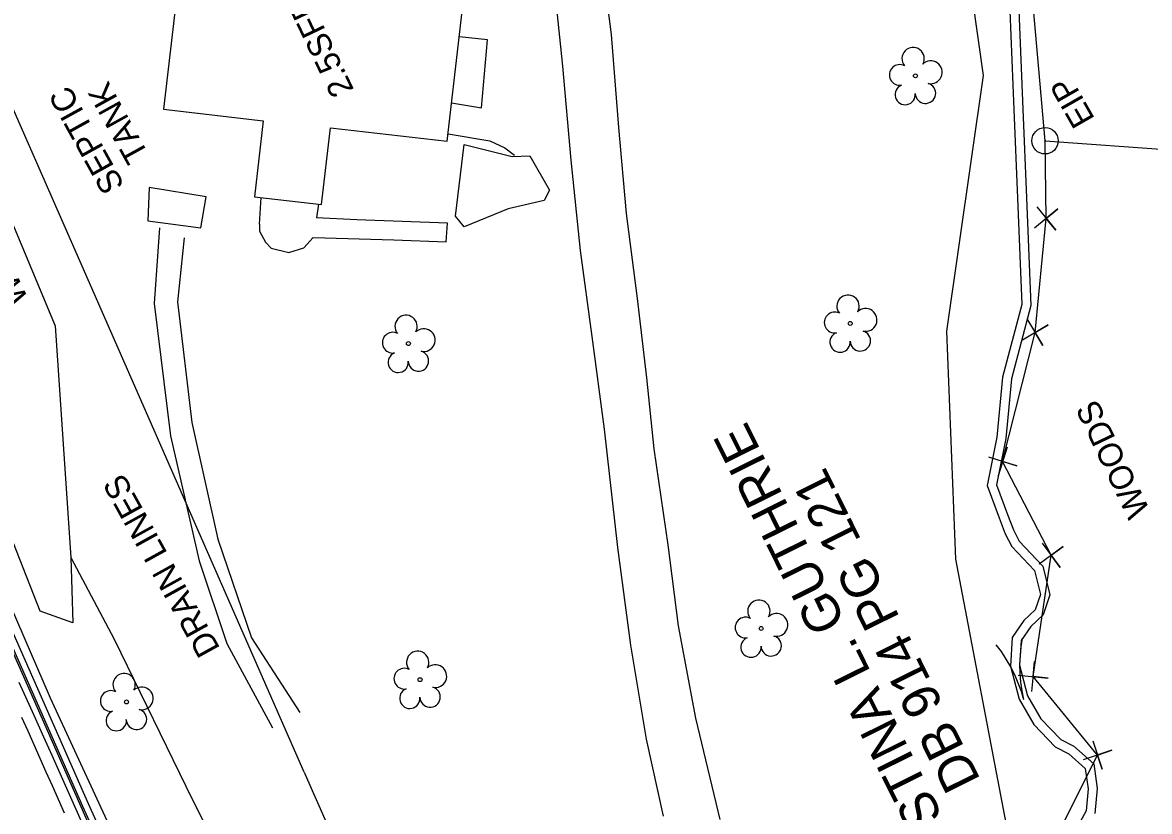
# Model space of a CAD drawing. Extents: x 472260 to 482161, y 489063 to 507124.
# Drawn here: x 475985.5 to 476173.2, y 501685.2 to 501816.7 of the extents above; entities that cross this region are included whole.
import ezdxf

# ---------------------------------------------------------------- set-up
doc = ezdxf.new("R2010")
doc.units = 0
for name, color, linetype in [('Exist Plan Preparation Watershed Blue', 7, 'Continuous'), ('Exist Roads EOP Other Cogo Number', 7, 'Continuous'), ('Exist Roads EOP Other Cogo Point CELL', 7, 'Continuous'), ('Exist Structure Minor Drop Inlet Cogo Comment', 7, 'Continuous'), ('Exist Structure Minor Drop Inlet Cogo Elevation', 7, 'Continuous'), ('Exist Structure Minor Drop Inlet Cogo Number', 7, 'Continuous'), ('Exist Structure Minor Pipes CMP 30 Inch Invert', 7, 'Continuous'), ('Exist Utilities Water Meter CELL', 7, 'Continuous'), ('Old_Level_51', 7, 'Continuous'), ('Prop Drainage Structure Catch Basin Convert From Junction Box Label', 7, 'Continuous'), ('Prop Drainage Structure Drop Inlet Grate 2 Narrow Slots and Sag Grates 840 24 CELL', 7, 'Continuous'), ('Prop Drainage Structure Drop Inlet Grate 2 Wide Slots and Flat Grates 840 20 Label', 7, 'Continuous'), ('Prop Drainage Structure Outlet Berm Ditch 850 10 CELL', 7, 'Continuous'), ('Prop Drainage Structure Pipe RCP 18in Class III', 7, 'Continuous'), ('Prop Drainage Structure Pipe RCP 24in Class III', 7, 'Continuous'), ('Prop Drainage Structure Pipe RCP 66in Class III', 7, 'Continuous'), ('Prop Drainage Structure Pipe Stub Out CELL', 7, 'Continuous'), ('Prop Drainage Structure Pipe Welded Steel 66in Label', 7, 'Continuous'), ('Prop Drainage Structure Plot Symbol 50 Scale CELL', 7, 'Continuous'), ('Prop Drainage Structure Tops and Inverts LABEL', 7, 'Continuous'), ('Prop Erosion Rip Rap Pad at Outlet Label', 7, 'Continuous'), ('Prop SS Cut Line', 7, 'Continuous'), ('Prop SS Fill Line', 7, 'Continuous'), ('Scratch_Level_7', 7, 'Continuous'), ('Scratch_Level_8', 7, 'Continuous')]:
    doc.layers.add(name, color=color, linetype=linetype)

msp = doc.modelspace()

# ---------------------------------------------------------------- linework, layer by layer
at = {"layer": 'Exist Plan Preparation Watershed Blue'}
for points in [[(476056.96, 501803.31), (476061.98, 501802.5), (476062.99, 501813.81), (476058.33, 501814.34)], [(476024.97, 501783.09), (476025.26, 501787.56)], [(476034.81, 501786.45), (476034.48, 501784.15)], [(476024.97, 501783.09), (476025.02, 501781.96), (476025.98, 501780.1), (476026.94, 501779.08), (476029.86, 501778.38), (476032.37, 501779.17), (476033.93, 501780.86), (476047.4, 501780.52), (476056.07, 501780.18), (476056.33, 501783.25), (476041.19, 501783.85), (476034.48, 501784.15)]]:
    msp.add_lwpolyline(points, dxfattribs=at)
at = {"layer": 'Exist Roads EOP Other Cogo Point CELL'}
for p, q in [((476156.05, 501784.05), (476156.05, 501784.05)), ((476154.22, 501765.03), (476154.22, 501765.03)), ((476148.79, 501743.56), (476148.79, 501743.56)), ((476156.88, 501727.91), (476156.88, 501727.91)), ((476153.87, 501707.7), (476153.87, 501707.7)), ((476164.59, 501694.62), (476164.59, 501694.62))]:
    msp.add_line(p, q, dxfattribs=at)
for points in [[(476154.46, 501785.98), (476157.64, 501782.12), (476156.05, 501784.05), (476157.98, 501785.64), (476154.12, 501782.46)], [(476152.94, 501767.18), (476155.5, 501762.88), (476154.22, 501765.03), (476156.37, 501766.31), (476152.08, 501763.75)], [(476146.41, 501744.32), (476151.18, 501742.8), (476148.79, 501743.56), (476149.55, 501745.95), (476148.04, 501741.18)], [(476155.4, 501729.92), (476158.37, 501725.9), (476156.88, 501727.91), (476158.89, 501729.4), (476154.87, 501726.42)], [(476151.38, 501707.95), (476156.35, 501707.46), (476153.87, 501707.7), (476154.11, 501710.19), (476153.62, 501705.22)], [(476163.81, 501696.99), (476165.38, 501692.25), (476164.59, 501694.62), (476166.97, 501695.41), (476162.22, 501693.83)]]:
    msp.add_lwpolyline(points, dxfattribs=at)
at = {"layer": 'Exist Structure Minor Drop Inlet Cogo Comment'}
for radius in [2.2, 0.0707]:
    msp.add_circle((476155.85, 501797.01), radius, dxfattribs=at)
at = {"layer": 'Exist Structure Minor Drop Inlet Cogo Elevation'}
msp.add_line((476032.41, 501691.77), (475818.42, 502179.8), dxfattribs=at)
msp.add_arc((478949.91, 502971.03), 3185.64, 203.67637, 207.50231, dxfattribs=at)
at = {"layer": 'Exist Structure Minor Drop Inlet Cogo Number'}
for p, q in [((476155.85, 501797.01), (476153.13, 501828.08)), ((476156.05, 501784.05), (476155.85, 501797.01)), ((476155.85, 501797.01), (476363.44, 501781.82)), ((476154.22, 501765.03), (476156.05, 501784.05)), ((476148.79, 501743.56), (476154.22, 501765.03)), ((476156.88, 501727.91), (476148.79, 501743.56)), ((476153.87, 501707.7), (476156.88, 501727.91)), ((476164.59, 501694.62), (476153.87, 501707.7)), ((476147.61, 501660.82), (476164.59, 501694.62))]:
    msp.add_line(p, q, dxfattribs=at)
at = {"layer": 'Exist Utilities Water Meter CELL'}
for points in [[(476008.34, 501782.5), (476007.43, 501769.91), (476010.17, 501747.81), (476014.97, 501727), (476019.54, 501713.2), (476027.14, 501699.18)], [(476012.47, 501780.85), (476011.36, 501770.18), (476013.73, 501750.07), (476018.08, 501730.61), (476023.67, 501714.17), (476031.72, 501701.71)]]:
    msp.add_lwpolyline(points, dxfattribs=at)
at = {"layer": 'Old_Level_51'}
msp.add_lwpolyline([(476016.1, 501787.65), (476006.64, 501789.24), (476006.38, 501783.69), (476015.2, 501782.49), (476016.1, 501787.65)], dxfattribs=at)
at = {"layer": 'Prop Drainage Structure Catch Basin Convert From Junction Box Label'}
for points in [[(476023.09, 501628.04), (476010.56, 501655.36), (475996.5, 501686.48), (475969.69, 501747.26), (475956.67, 501777.09), (475945.34, 501802.97), (475931.42, 501835.01), (475919.05, 501863.11), (475906.12, 501892.94), (475902.03, 501902.25)], [(476022.19, 501627.62), (476009.65, 501654.95), (475995.58, 501686.07), (475968.77, 501746.86), (475955.75, 501776.69), (475944.43, 501802.57), (475930.5, 501834.61), (475918.13, 501862.71), (475906.55, 501889.43)]]:
    msp.add_lwpolyline(points, dxfattribs=at)
at = {"layer": 'Prop Drainage Structure Drop Inlet Grate 2 Narrow Slots and Sag Grates 840 24 CELL'}
msp.add_lwpolyline([(475992.51, 501684.91), (475991.5, 501687.19), (475990.49, 501689.47), (475989.47, 501691.75), (475988.46, 501694.03), (475987.45, 501696.32), (475986.44, 501698.6), (475985.43, 501700.88)], dxfattribs=at)
at = {"layer": 'Prop Drainage Structure Drop Inlet Grate 2 Wide Slots and Flat Grates 840 20 Label'}
for p, q in [((476134.26, 501807.83), (476134.26, 501807.83)), ((476123.41, 501766.56), (476123.41, 501766.56)), ((476049.8, 501763.2), (476049.8, 501763.2)), ((476108.57, 501715.72), (476108.57, 501715.72)), ((476051.74, 501707.19), (476051.74, 501707.19)), ((476002.84, 501703.47), (476002.84, 501703.47))]:
    msp.add_line(p, q, dxfattribs=at)
for centre in [(476134.26, 501807.83), (476123.41, 501766.56), (476049.8, 501763.2), (476108.57, 501715.72), (476051.74, 501707.19), (476002.84, 501703.47)]:
    msp.add_circle(centre, 0.326, dxfattribs=at)
for centre, radius, start, end in [((476133.88, 501810.7), 1.86, 330.1651, 219.7134), ((476136.81, 501808.42), 1.9, 257.1011, 134.1999), ((476131.66, 501807.98), 1.73, 62.6636, 279.3457), ((476135.94, 501804.93), 1.7, 181.2822, 74.56), ((476132.56, 501804.71), 1.69, 111.5671, 6.231), ((476123.03, 501769.44), 1.86, 330.1651, 219.7134), ((476125.96, 501767.15), 1.9, 257.1011, 134.1999), ((476049.41, 501766.07), 1.86, 330.1651, 219.7134), ((476120.81, 501766.72), 1.73, 62.6636, 279.3457), ((476047.19, 501763.35), 1.73, 62.6636, 279.3457), ((476052.35, 501763.78), 1.9, 257.1011, 134.1999), ((476125.09, 501763.66), 1.7, 181.2822, 74.56), ((476121.71, 501763.44), 1.69, 111.5671, 6.231), ((476048.1, 501760.07), 1.69, 111.5671, 6.231), ((476051.47, 501760.3), 1.7, 181.2822, 74.56), ((476108.19, 501718.59), 1.86, 330.1651, 219.7134), ((476111.12, 501716.31), 1.9, 257.1011, 134.1999), ((476105.97, 501715.87), 1.73, 62.6636, 279.3457), ((476110.24, 501712.82), 1.7, 181.2822, 74.56), ((476106.87, 501712.6), 1.69, 111.5671, 6.231), ((476051.35, 501710.07), 1.86, 330.1651, 219.7134), ((476049.13, 501707.35), 1.73, 62.6636, 279.3457), ((476054.28, 501707.78), 1.9, 257.1011, 134.1999), ((476002.45, 501706.35), 1.86, 330.1651, 219.7134), ((476000.23, 501703.63), 1.73, 62.6636, 279.3457), ((476005.39, 501704.06), 1.9, 257.1011, 134.1999), ((476050.03, 501704.07), 1.69, 111.5671, 6.231), ((476053.41, 501704.29), 1.7, 181.2822, 74.56), ((476001.13, 501700.35), 1.69, 111.5671, 6.231), ((476004.51, 501700.57), 1.7, 181.2822, 74.56)]:
    msp.add_arc(centre, radius, start, end, dxfattribs=at)
at = {"layer": 'Prop Drainage Structure Pipe RCP 18in Class III'}
for points in [[(476081.6, 501830.22), (476083.56, 501814.7), (476084.8, 501799.24), (476086.08, 501784.87), (476087.92, 501770.74), (476089.49, 501757.5), (476090.7, 501745.66), (476093, 501729.64), (476094.73, 501716.14), (476097.61, 501700.79), (476101.69, 501683.88)], [(476092.31, 501684.44), (476089.46, 501697.28), (476086.83, 501712.92), (476084.68, 501729.2), (476082.47, 501748.93), (476080.42, 501764.36), (476078.47, 501778.7), (476076.9, 501793.78), (476075.53, 501809.47), (476074.4, 501820.17)]]:
    msp.add_lwpolyline(points, dxfattribs=at)
at = {"layer": 'Prop Drainage Structure Pipe RCP 24in Class III'}
for points in [[(476149.82, 501822.82), (476150.66, 501802.24), (476151.24, 501787.46), (476151.99, 501769.69), (476148.76, 501757.6), (476147.82, 501747.59), (476146.22, 501739.55), (476148.21, 501734.17), (476149.22, 501731.52), (476150.34, 501729.38), (476154.1, 501725.37)], [(476151.32, 501822.93), (476152.16, 501802.3), (476152.74, 501787.52), (476153.5, 501769.53), (476150.24, 501757.33), (476149.31, 501747.37), (476147.78, 501739.67), (476149.61, 501734.7), (476150.59, 501732.14), (476151.57, 501730.26), (476155.46, 501726.12)], [(476155.46, 501726.12), (476156.66, 501721.33), (476155.53, 501717.98), (476153.47, 501716.05), (476151.86, 501713.71), (476151.6, 501709.61), (476152.93, 501704.48), (476155.18, 501700.64), (476158.46, 501697.21), (476160.64, 501696.08), (476163.96, 501693.14), (476164.53, 501689.03), (476164.14, 501684.88)], [(476154.1, 501725.37), (476155.1, 501721.39), (476154.23, 501718.82), (476152.33, 501717.03), (476150.39, 501714.21), (476150.09, 501709.46), (476151.53, 501703.91), (476153.97, 501699.73), (476157.55, 501696), (476159.79, 501694.83), (476162.55, 501692.38), (476163.02, 501688.99), (476162.68, 501685.32), (476161.1, 501682.36)]]:
    msp.add_lwpolyline(points, dxfattribs=at)
at = {"layer": 'Prop Drainage Structure Pipe Stub Out CELL'}
msp.add_lwpolyline([(475984.92, 501706.77), (475986.31, 501703.71), (475987.68, 501700.66), (475989.04, 501697.63), (475990.38, 501694.62), (475991.71, 501691.61), (475993.05, 501688.61), (475994.38, 501685.61), (475995.71, 501682.61)], dxfattribs=at)
at = {"layer": 'Prop Drainage Structure Plot Symbol 50 Scale CELL'}
msp.add_lwpolyline([(475858.22, 502003.88), (475873.57, 501964.57), (475891.99, 501921.71), (475909.74, 501881.21), (475923.46, 501849.74), (475940.91, 501809.98), (475962.4, 501760.56), (475980.02, 501720.44), (476000.62, 501673.83), (476022.76, 501626.04)], dxfattribs=at)
at = {"layer": 'Prop Drainage Structure Tops and Inverts LABEL'}
for points in [[(476022.28, 501634.99), (476006.38, 501668.99), (475990.19, 501704.12), (475956.28, 501782.58), (475939.62, 501821.15), (475932.88, 501836.43), (475938.29, 501838.59)], [(476057.63, 501784.45), (476059.07, 501796.41), (476067.09, 501794.36), (476070.05, 501794.52), (476073.33, 501788.76), (476072.41, 501787.04), (476066.4, 501785.69), (476059.1, 501782.68), (476057.63, 501784.45)], [(475993.54, 501727.54), (476000.81, 501713.95), (476013.85, 501687.14), (476026.43, 501662.24), (476033.03, 501643.73)]]:
    msp.add_lwpolyline(points, dxfattribs=at)
at = {"layer": 'Prop Erosion Rip Rap Pad at Outlet Label'}
for points in [[(476140.99, 501727.29), (476139.47, 501765.27), (476145.59, 501807.86), (476138.11, 501860.9), (476086.9, 501921.65), (476072.81, 501972.58), (476078.45, 501996.77), (476071.32, 502007.46), (476040.62, 501992.73), (475998.06, 501960.08), (475920.84, 501910.21)], [(475977.25, 501798.93), (475990.98, 501766.15), (475993.54, 501727.54), (475993.91, 501716.65), (475988.46, 501718.62), (475952.41, 501810.41)], [(476187.79, 501751.97), (476187.19, 501730.04), (476202.62, 501717.27), (476190.92, 501678.08), (476166.08, 501679.55), (476149.37, 501683.26), (476140.99, 501727.29)]]:
    msp.add_lwpolyline(points, dxfattribs=at)
at = {"layer": 'Prop SS Fill Line'}
msp.add_lwpolyline([(476056.26, 501796.92), (476060.39, 501832.55), (476013.18, 501838.03), (476009.03, 501802.25), (476025.63, 501800.33), (476024.17, 501787.69), (476035.35, 501786.39), (476036.83, 501799.17)], close=True, dxfattribs=at)
msp.add_lwpolyline([(476056.4, 501798.15), (476063.38, 501796.99), (476065.84, 501795.82), (476067.45, 501794.63)], dxfattribs=at)
at = {"layer": 'Scratch_Level_8'}
msp.add_line((476151.06, 501708.72), (476151.06, 501708.72), dxfattribs=at)
for points in [[(476147.63, 501713.01), (476148.53, 501711.86), (476149.33, 501710.59), (476150.1, 501709.33), (476150.74, 501708.03), (476151.33, 501706.67), (476151.85, 501705.27), (476152.28, 501703.87)], [(476152.06, 501714.12), (476151.81, 501712.68), (476151.7, 501711.18), (476151.62, 501709.71), (476151.66, 501708.26), (476151.79, 501706.79), (476151.99, 501705.3), (476152.28, 501703.87)]]:
    msp.add_lwpolyline(points, dxfattribs=at)

# ---------------------------------------------------------------- texts
at = {"layer": 'Exist Roads EOP Other Cogo Number'}
msp.add_text('EIP', height=4, rotation=119.7387, dxfattribs=at).set_placement((476164.23, 501800.65))
at = {"layer": 'Exist Structure Minor Pipes CMP 30 Inch Invert'}
for s, p in [('TANK', (476006.64, 501794.65)), ('SEPTIC', (476002.59, 501789.57))]:
    msp.add_text(s, height=4, rotation=118.9347, dxfattribs=at).set_placement(p)
at = {"layer": 'Prop Drainage Structure Outlet Berm Ditch 850 10 CELL'}
msp.add_text('2.5SFBKD', height=4, rotation=115.5025, dxfattribs=at).set_placement((476040.79, 501805.49))
at = {"layer": 'Prop Drainage Structure Pipe RCP 66in Class III'}
for p in [(475986.6, 501770.52), (476173.42, 501735.32)]:
    msp.add_text('WOODS', height=4, rotation=115.5025, dxfattribs=at).set_placement(p)
at = {"layer": 'Prop Drainage Structure Pipe Welded Steel 66in Label'}
msp.add_text('DB 914 PG 121', height=6.25, rotation=116.4407, dxfattribs=at).set_placement((476145.19, 501690.44))
at = {"layer": 'Prop SS Cut Line'}
msp.add_text('DRAIN LINES', height=4, rotation=118.9347, dxfattribs=at).set_placement((476018.51, 501712.37))
at = {"layer": 'Scratch_Level_7'}
msp.add_text('CHRISTINA L. GUTHRIE', height=6.25, rotation=116.4407, dxfattribs=at).set_placement((476148.01, 501666.01))

doc.saveas('drawing.dxf')
